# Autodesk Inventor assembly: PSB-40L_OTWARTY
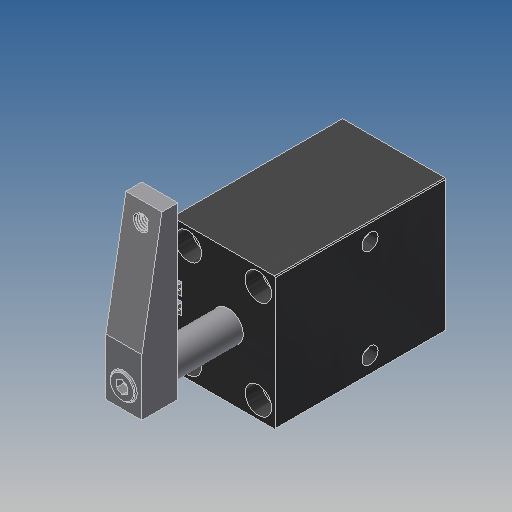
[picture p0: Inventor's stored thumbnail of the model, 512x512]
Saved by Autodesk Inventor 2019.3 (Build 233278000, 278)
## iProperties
Company: Î¢ÈíÖÐ¹ú
Created: 2013-10
Part Number: PSB-40L_OTWARTY
Material: Ogólny
Description: STEP AP203
Document SubType Name: Assembly
Designer: CADENGINEERING4
Sending System: SolidWorks 2012
Preprocessor: SwSTEP 2.0
Title: PSB-40.STEP
Author: Î¢ÈíÓÃ»§
Revision Number: ÈÎºÎ
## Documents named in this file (6)
- E:\SERWER_ZAPAS\Pneumatic\PSB PNEUMATIC SWING\PSB-40\PSB-40L_OTWARTY.iam
- E:\SERWER_ZAPAS\Pneumatic\PSB PNEUMATIC SWING\PSB-40\PSB40BT.ipt
- E:\SERWER_ZAPAS\Pneumatic\PSB PNEUMATIC SWING\PSB-40\PSB40HSG.ipt
- E:\SERWER_ZAPAS\Pneumatic\PSB PNEUMATIC SWING\PSB-40\PSB40YB.ipt
- E:\SERWER_ZAPAS\Pneumatic\PSB PNEUMATIC SWING\PSB-40\PSB40HG.ipt
- E:\SERWER_ZAPAS\Pneumatic\PSB PNEUMATIC SWING\PSB-40\socket head cap screw_iso_ISO 4762 M8 x 25 --- 25S.ipt
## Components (5 placed, 5 different names)
1. PSB40BT_1 — Zestawiające:1, Zestawiające:7, Kątowe:1
2. PSB40HSG_2 — Zestawiające:1, Zestawiające:3, Zestawiające:4, Zestawiające:7
3. PSB40YB_3 — Zestawiające:3, Zestawiające:4, Zestawiające:5, Zestawiające:6, Kątowe:1
4. PSB40HG_4
5. socket head cap screw_iso_ISO 4762 M8 x 25 --- 25S_5 — Zestawiające:5, Zestawiające:6
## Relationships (7: Mate 6, Angle 1)
- Zestawiające:1 [Mate]: PSB40BT_1 ↔ PSB40HSG_2
- Zestawiające:3 [Mate]: PSB40HSG_2 ↔ PSB40YB_3
- Zestawiające:4 [Mate]: PSB40HSG_2 ↔ PSB40YB_3
- Zestawiające:5 [Mate]: PSB40YB_3 ↔ socket head cap screw_iso_ISO 4762 M8 x 25 --- 25S_5
- Zestawiające:6 [Mate]: PSB40YB_3 ↔ socket head cap screw_iso_ISO 4762 M8 x 25 --- 25S_5
- Zestawiające:7 [Mate]: PSB40BT_1 ↔ PSB40HSG_2
- Kątowe:1 [Angle]: PSB40BT_1 ↔ PSB40YB_3
